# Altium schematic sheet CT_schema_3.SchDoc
size 591 x 347 mm
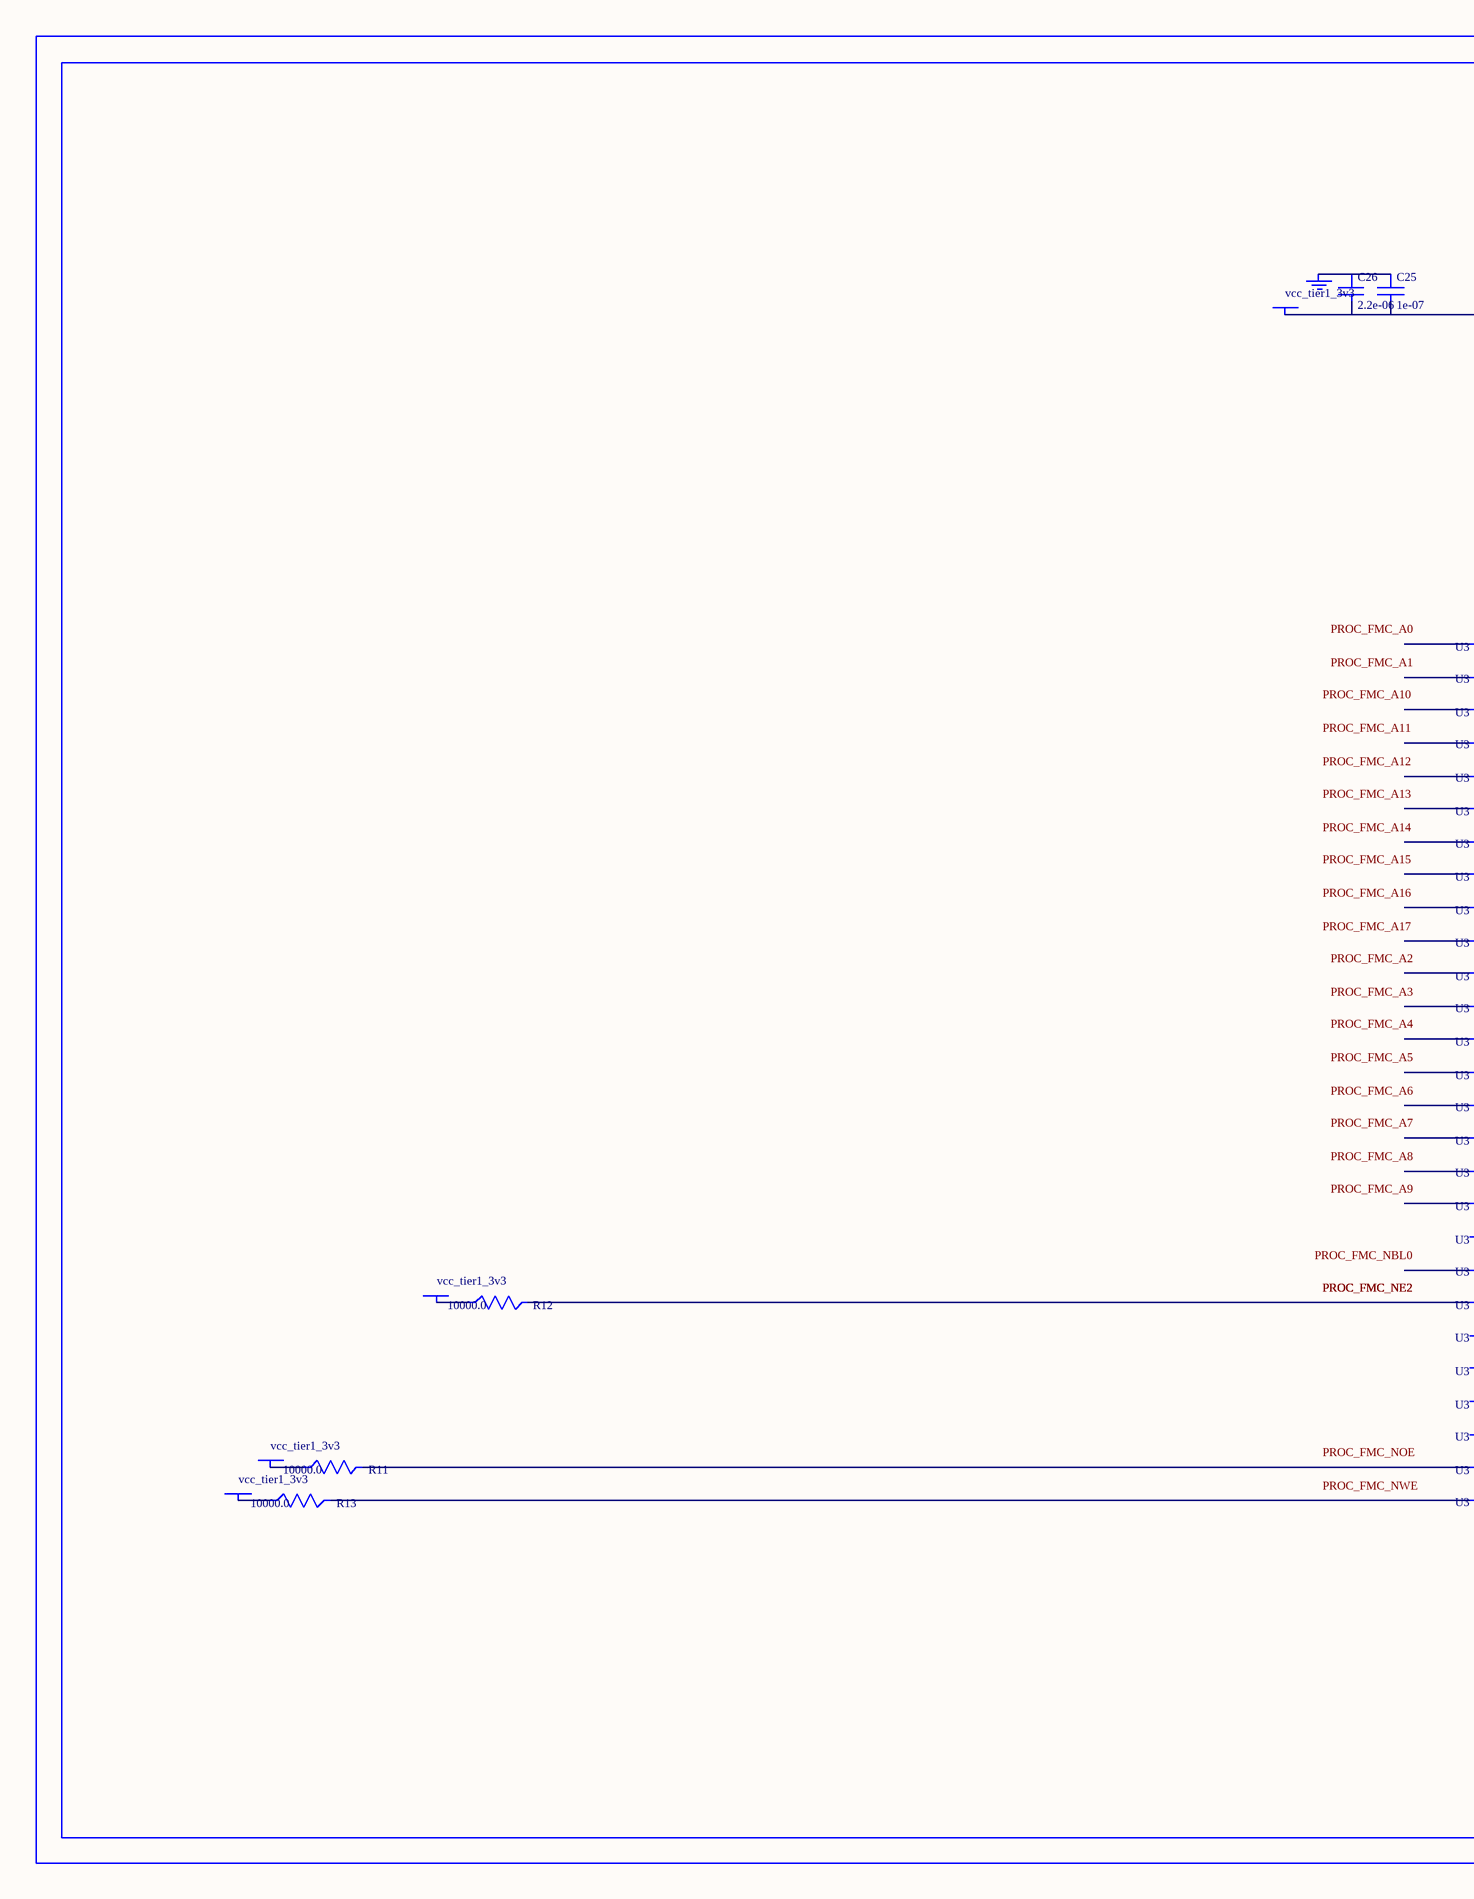
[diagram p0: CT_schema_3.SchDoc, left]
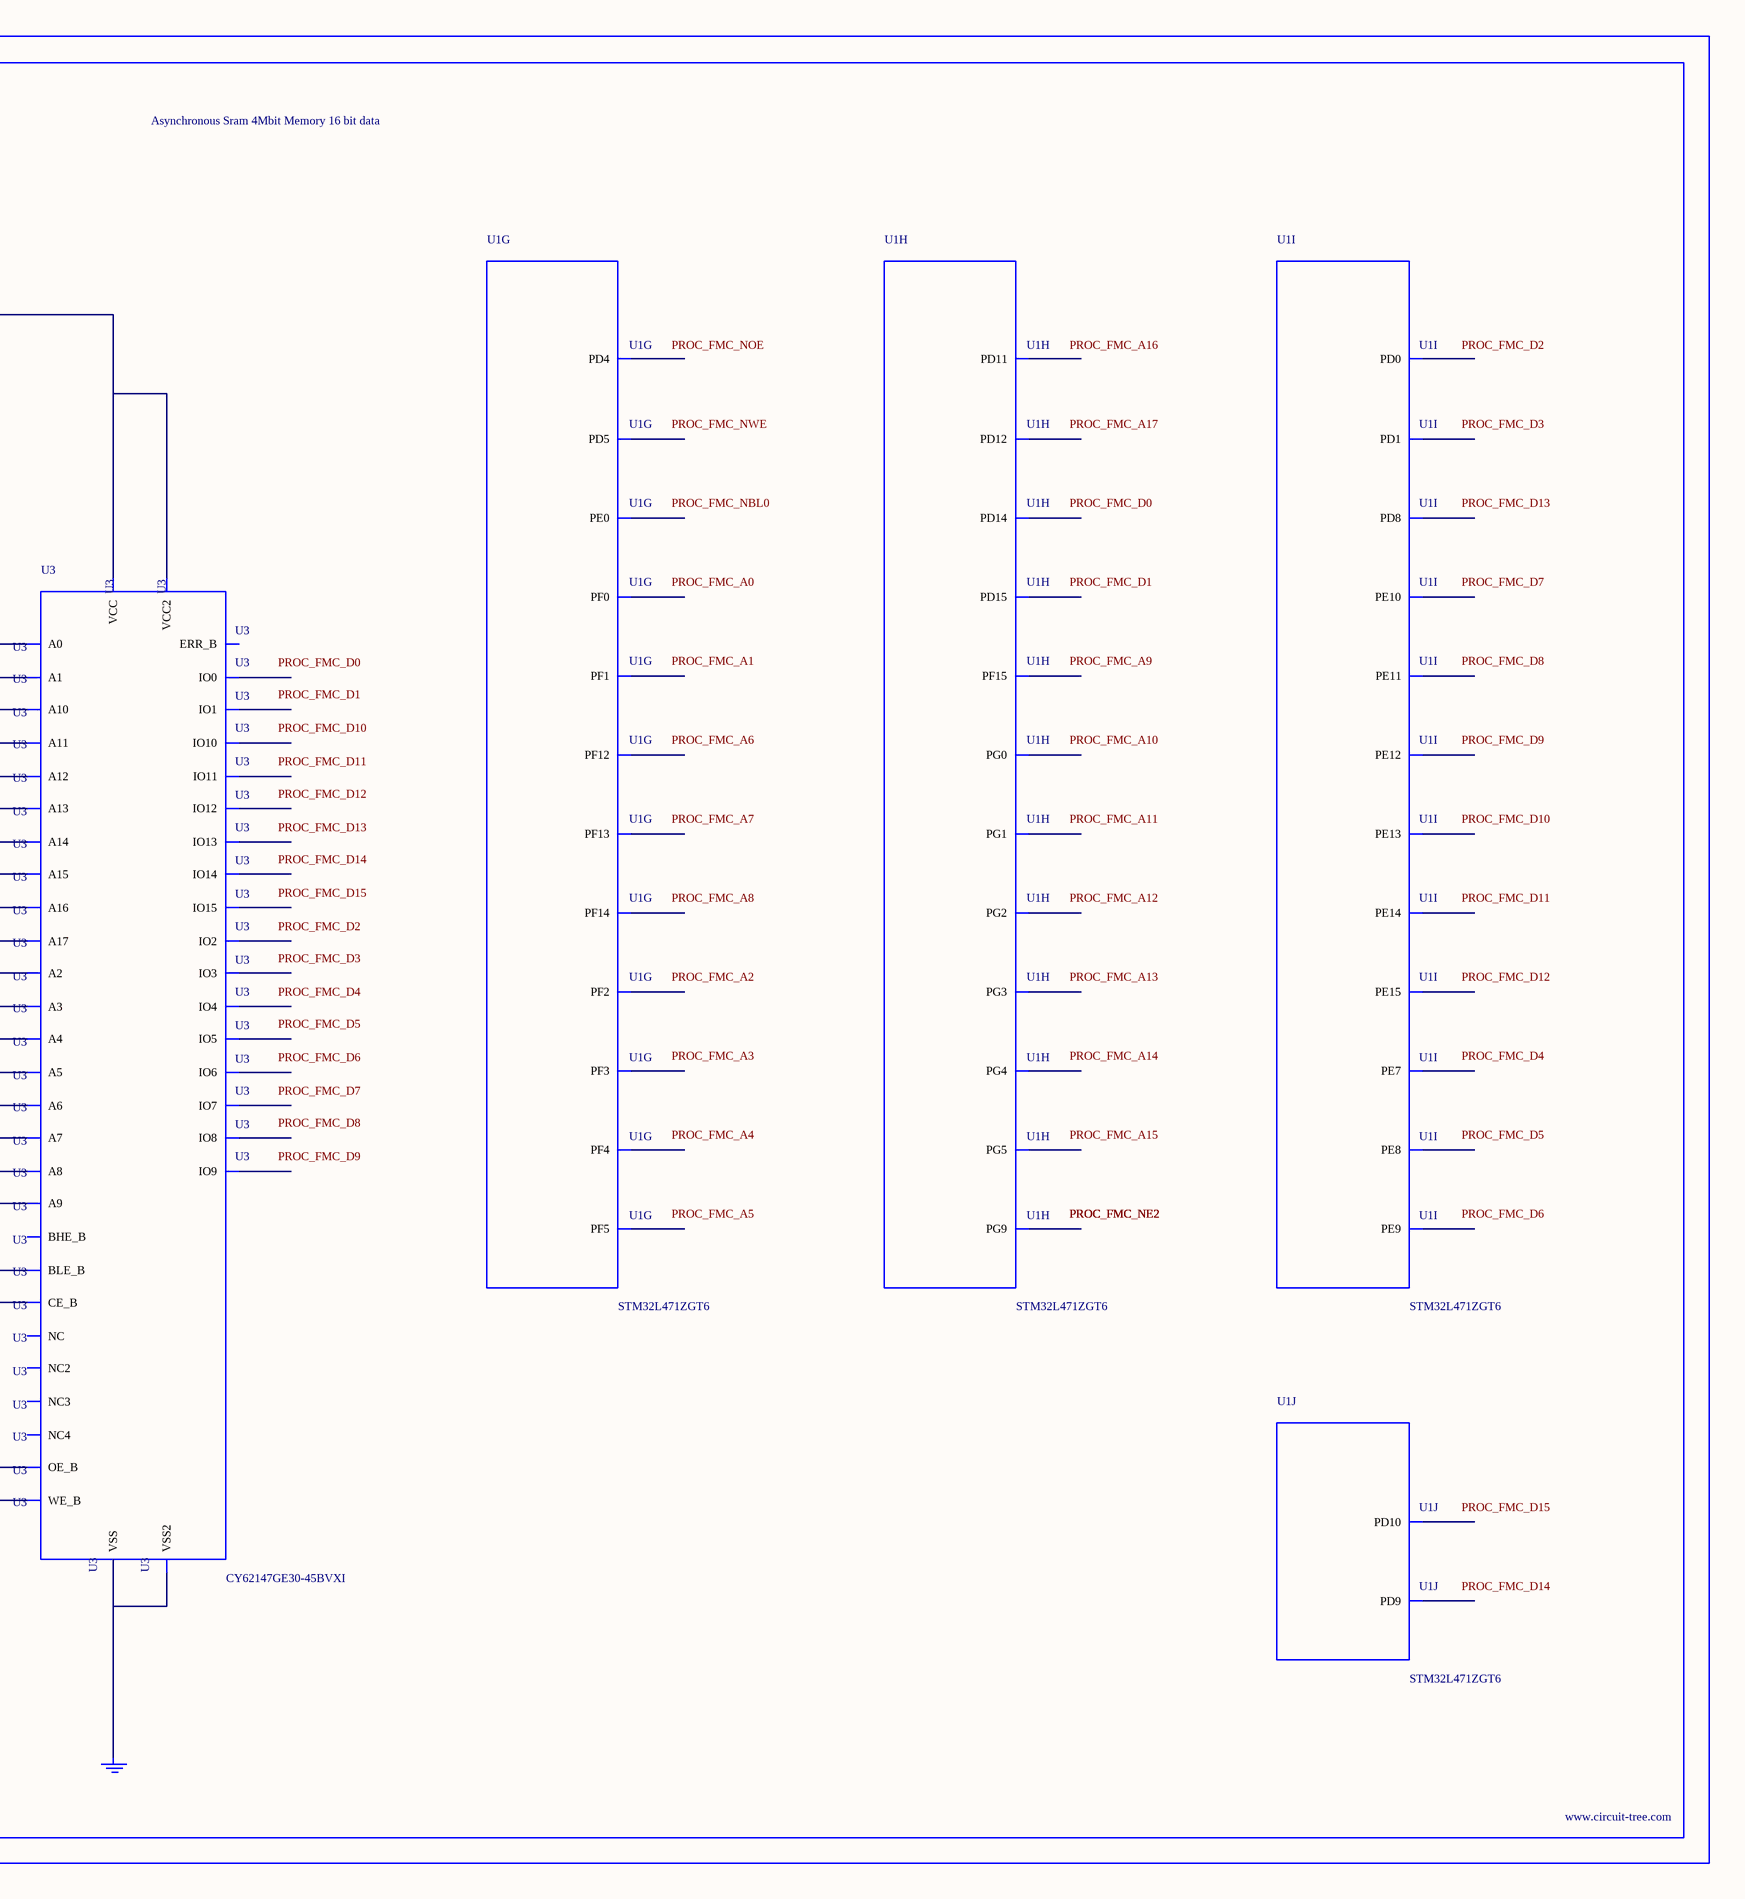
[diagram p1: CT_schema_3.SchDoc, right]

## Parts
BORDER2  (no value)
C25  1e-07  [C0402]
C26  2.2e-06  [C0603]
GND_INSTANCE_2_0  (no value)
GND_INSTANCE_2_1  (no value)
POWER_INSTANCE_2_0  vcc_tier1_3v3
POWER_INSTANCE_2_1  vcc_tier1_3v3
POWER_INSTANCE_2_2  vcc_tier1_3v3
POWER_INSTANCE_2_3  vcc_tier1_3v3
R11  10000.0  [R0603]
R12  10000.0  [R0603]
R13  10000.0  [R0603]
U1  STM32L471ZGT6  [LQFP144]  (parts G,H,I,J of 14)
U3  CY62147GE30-45BVXI  [VFBGA48]

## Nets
NetC25_1: C25.1 C26.1 GND_INSTANCE_2_0.0(GND)
NetC25_2: C25.2 C26.2 POWER_INSTANCE_2_0.0(PWR) U3.D6(VCC) U3.E1(VCC2)
NetGND_INSTANCE_2_1_0: GND_INSTANCE_2_1.0(GND) U3.D1(VSS) U3.E6(VSS2)
NetPOWER_INSTANCE_2_1_0: POWER_INSTANCE_2_1.0(PWR) R11.1
NetPOWER_INSTANCE_2_2_0: POWER_INSTANCE_2_2.0(PWR) R12.1
NetPOWER_INSTANCE_2_3_0: POWER_INSTANCE_2_3.0(PWR) R13.1
NetR11_2: R11.2 U3.A2(OE_B)
NetR12_2: R12.2 U3.B5(CE_B)
NetR13_2: R13.2 U3.G5(WE_B)

Not connected (* = marked no-connect by the designer): U1 10(PF0) 11(PF1) 12(PF2) 13(PF3) 14(PF4) 15(PF5) 50(PF12) 53(PF13) 54(PF14) 55(PF15) 56(PG0) 57(PG1) 58(PE7) 59(PE8) 60(PE9) 63(PE10) 64(PE11) 65(PE12) 66(PE13) 67(PE14) 68(PE15) 77(PD8) 78(PD9) 79(PD10) 80(PD11) 81(PD12) 85(PD14) 86(PD15) 87(PG2) 88(PG3) 89(PG4) 90(PG5) 114(PD0) 115(PD1) 118(PD4) 119(PD5) 124(PG9) 141(PE0); U3 A1(BLE_B) A3(A0) A4(A1) A5(A2) A6(NC) B1(IO8) B2(BHE_B) B3(A3) B4(A4) B6(IO0) C1(IO9) C2(IO10) C3(A5) C4(A6) C5(IO1) C6(IO2) D2(IO11) D3(A17) D4(A7) D5(IO3) E2(IO12) E3(ERR_B) E4(A16) E5(IO4) F1(IO14) F2(IO13) F3(A14) F4(A15) F5(IO5) F6(IO6) G1(IO15) G2(NC2) G3(A12) G4(A13) G6(IO7) H1(NC3) H2(A8) H3(A9) H4(A10) H5(A11) H6(NC4)

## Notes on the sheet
- Labels drawn without touching a wire or pin: PROC_FMC_A0, PROC_FMC_A1, PROC_FMC_A2, PROC_FMC_A3, PROC_FMC_A4, PROC_FMC_A5, PROC_FMC_A6, PROC_FMC_A7, PROC_FMC_A8, PROC_FMC_A9, PROC_FMC_A10, PROC_FMC_A11, PROC_FMC_A12, PROC_FMC_A13, PROC_FMC_A14, PROC_FMC_A15, PROC_FMC_A16, PROC_FMC_A17, PROC_FMC_D0, PROC_FMC_D1, PROC_FMC_D2, PROC_FMC_D3, PROC_FMC_D4, PROC_FMC_D5, PROC_FMC_D6, PROC_FMC_D7, PROC_FMC_D8, PROC_FMC_D9, PROC_FMC_D10, PROC_FMC_D11, PROC_FMC_D12, PROC_FMC_D13, PROC_FMC_D14, PROC_FMC_D15, PROC_FMC_NBL0, PROC_FMC_NOE, PROC_FMC_NWE

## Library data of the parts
BORDER2 = BORDER_PAGE2
C25 = C0402C104K3RACTU
C26 = C0603C225K8RACTU
GND_INSTANCE_2_0 GND_INSTANCE_2_1 = GND
POWER_INSTANCE_2_0-POWER_INSTANCE_2_3 = PWR
R11-R13 = RC0603JR-0710KL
